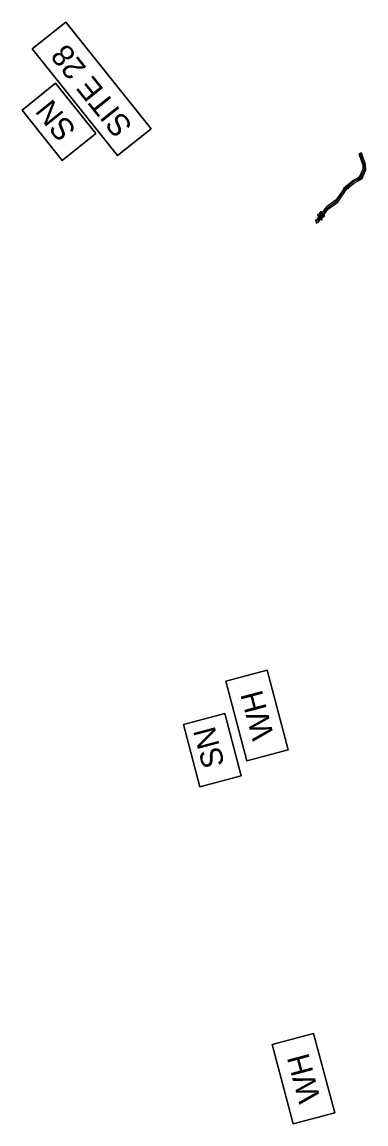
# Model space of a CAD drawing. Extents: x 474218 to 481634, y 484357 to 504997.
# Drawn here: x 474218 to 474451, y 504250 to 504997 of the extents above; entities that cross this region are included whole.
import ezdxf

# ---------------------------------------------------------------- set-up
doc = ezdxf.new("R2010")
doc.units = 0
for name, color, linetype in [('Exist Hydro Jurisdictional Stream or Body of Water', 7, 'Continuous'), ('Old_Level_29', 7, 'Continuous'), ('Old_Level_30', 7, 'Continuous'), ('Prop Earthen Structure Impacts In Surface Waters Hatching CELL', 7, 'Continuous'), ('Prop Grid Mask', 7, 'Continuous'), ('Scratch_Level_4', 7, 'Continuous'), ('Temp Earthen Structure Impacts In Surface Waters Hatching CELL', 7, 'Continuous')]:
    doc.layers.add(name, color=color, linetype=linetype)

msp = doc.modelspace()

# ---------------------------------------------------------------- linework, layer by layer
at = {"layer": 'Exist Hydro Jurisdictional Stream or Body of Water'}
for points in [[(474245.29, 504903.39), (474217.97, 504937.53), (474240.68, 504955.71), (474268, 504921.57)], [(474338.65, 504478.69), (474327.42, 504520.95), (474355.53, 504528.42), (474366.75, 504486.16)]]:
    msp.add_lwpolyline(points, close=True, dxfattribs=at)
at = {"layer": 'Old_Level_29'}
msp.add_lwpolyline([(474282.77, 504906.7), (474224.88, 504979.04), (474247.59, 504997.21), (474305.48, 504924.87)], close=True, dxfattribs=at)
at = {"layer": 'Old_Level_30'}
for points in [[(474370.47, 504496.26), (474356.14, 504550.18), (474384.25, 504557.65), (474398.57, 504503.73)], [(474402.03, 504250.05), (474387.7, 504303.96), (474415.81, 504311.43), (474430.13, 504257.51)]]:
    msp.add_lwpolyline(points, close=True, dxfattribs=at)
at = {"layer": 'Prop Earthen Structure Impacts In Surface Waters Hatching CELL'}
for p, q in [((474448.29, 504908.46), (474446.4, 504907.79)), ((474423.86, 504871.15), (474425.07, 504869.38))]:
    msp.add_line(p, q, dxfattribs=at)
for points in [[(474446.4, 504907.79), (474449.1, 504900.21), (474449.28, 504897.46), (474446.74, 504891.92), (474442.62, 504889.81), (474436.75, 504884.72), (474431, 504876.77), (474424.57, 504871.98), (474423.86, 504871.15)], [(474425.07, 504869.38), (474425.98, 504870.53), (474432.15, 504875.13), (474438.37, 504884.15), (474443.26, 504887.92), (474448.49, 504890.93), (474451.31, 504897.08), (474451.07, 504900.62), (474448.29, 504908.46)]]:
    msp.add_lwpolyline(points, dxfattribs=at)
for points in [[(474447.51, 504890.45), (474447.61, 504890.54), (474447.19, 504891.06), (474447.14, 504890.92), (474446.99, 504890.78), (474446.99, 504890.78), (474446.94, 504890.76), (474446.81, 504890.72), (474446.74, 504890.73), (474446.65, 504890.75), (474446.61, 504890.76), (474446.59, 504890.77), (474446.52, 504890.83), (474446.42, 504890.9), (474445.81, 504891.66), (474445.78, 504891.6), (474445.75, 504891.37), (474445.74, 504891.31), (474445.81, 504890.98), (474446.35, 504890.3), (474446.63, 504890.2), (474446.71, 504890.17), (474446.92, 504890.18), (474447, 504890.18), (474447.04, 504890.18), (474447.06, 504890.18), (474447.07, 504890.18), (474447.1, 504890.2), (474447.15, 504890.22), (474447.19, 504890.24), (474447.31, 504890.29), (474447.36, 504890.31), (474447.37, 504890.32)], [(474446.28, 504891.38), (474446.31, 504891.54), (474446.06, 504891.66), (474445.97, 504891.69), (474445.86, 504891.75), (474445.84, 504891.72), (474445.84, 504891.71), (474445.83, 504891.69), (474445.81, 504891.66), (474446.42, 504890.9), (474446.29, 504891.11), (474446.29, 504891.15), (474446.28, 504891.17), (474446.28, 504891.22), (474446.26, 504891.33)], [(474446.32, 504890.33), (474446.35, 504890.3), (474445.81, 504890.98), (474445.81, 504890.97), (474446.03, 504890.59), (474446.03, 504890.59)], [(474448.34, 504892.7), (474448.51, 504892.55), (474447.9, 504893.32), (474447.85, 504893.31), (474447.85, 504893.31), (474447.84, 504893.31), (474447.76, 504893.3), (474447.73, 504893.29), (474447.71, 504893.28), (474447.62, 504893.23), (474447.58, 504893.21), (474447.54, 504893.2), (474447.42, 504893.14), (474447.36, 504893.08), (474447.22, 504892.94), (474447.16, 504892.88), (474447.13, 504892.8), (474447.07, 504892.66), (474447.07, 504892.66), (474447.03, 504892.55), (474447.03, 504892.43), (474447.03, 504892.16), (474447.05, 504892.08), (474447.12, 504891.73), (474447.16, 504891.56), (474447.75, 504890.82), (474447.76, 504890.93), (474447.79, 504891.15), (474447.78, 504891.23), (474447.73, 504891.56), (474447.69, 504891.71), (474447.64, 504891.95), (474447.58, 504892.24), (474447.6, 504892.33), (474447.61, 504892.45), (474447.72, 504892.63), (474447.79, 504892.67), (474447.91, 504892.74), (474447.95, 504892.75), (474448, 504892.76), (474448.11, 504892.78), (474448.15, 504892.77), (474448.2, 504892.76), (474448.32, 504892.71), (474448.33, 504892.71)], [(474447.71, 504890.75), (474447.75, 504890.82), (474447.16, 504891.56), (474447.21, 504891.38), (474447.22, 504891.12), (474447.19, 504891.06), (474447.61, 504890.54), (474447.64, 504890.6)], [(474449.18, 504892.43), (474448.94, 504892.86), (474448.56, 504893.2), (474448.56, 504893.2), (474448.18, 504893.33), (474448.14, 504893.34), (474447.9, 504893.32), (474448.51, 504892.55), (474448.65, 504892.32), (474448.65, 504892.32), (474448.65, 504892.3), (474448.68, 504892.15), (474448.69, 504892.09), (474448.69, 504892.06), (474448.66, 504891.93), (474448.65, 504891.88), (474448.63, 504891.84), (474448.56, 504891.72), (474448.84, 504891.58), (474448.91, 504891.54), (474449.01, 504891.5), (474449.07, 504891.59), (474449.08, 504891.61), (474449.1, 504891.63), (474449.14, 504891.69), (474449.14, 504891.7), (474449.14, 504891.71), (474449.15, 504891.75), (474449.22, 504891.99), (474449.23, 504892.02), (474449.18, 504892.43)], [(474437.9, 504883.31), (474438, 504883.4), (474437.58, 504883.92), (474437.53, 504883.78), (474437.39, 504883.65), (474437.38, 504883.64), (474437.33, 504883.62), (474437.2, 504883.58), (474437.13, 504883.6), (474437.04, 504883.61), (474437, 504883.62), (474436.98, 504883.64), (474436.91, 504883.69), (474436.81, 504883.76), (474436.2, 504884.52), (474436.17, 504884.47), (474436.14, 504884.23), (474436.13, 504884.18), (474436.2, 504883.85), (474436.74, 504883.17), (474437.02, 504883.06), (474437.1, 504883.03), (474437.32, 504883.04), (474437.39, 504883.04), (474437.43, 504883.04), (474437.46, 504883.05), (474437.46, 504883.05), (474437.49, 504883.06), (474437.54, 504883.08), (474437.58, 504883.1), (474437.71, 504883.16), (474437.75, 504883.17), (474437.76, 504883.18)], [(474436.67, 504884.25), (474436.7, 504884.41), (474436.45, 504884.52), (474436.36, 504884.56), (474436.25, 504884.61), (474436.23, 504884.58), (474436.23, 504884.58), (474436.22, 504884.55), (474436.2, 504884.52), (474436.81, 504883.76), (474436.68, 504883.97), (474436.68, 504884.02), (474436.68, 504884.03), (474436.67, 504884.08), (474436.66, 504884.19)], [(474436.71, 504883.2), (474436.74, 504883.17), (474436.2, 504883.85), (474436.2, 504883.83), (474436.42, 504883.46), (474436.42, 504883.46)], [(474438.74, 504885.56), (474438.9, 504885.41), (474438.29, 504886.18), (474438.24, 504886.18), (474438.24, 504886.18), (474438.23, 504886.18), (474438.15, 504886.17), (474438.12, 504886.16), (474438.1, 504886.15), (474438.01, 504886.1), (474437.97, 504886.08), (474437.94, 504886.06), (474437.81, 504886), (474437.76, 504885.94), (474437.61, 504885.8), (474437.55, 504885.74), (474437.52, 504885.67), (474437.46, 504885.52), (474437.46, 504885.52), (474437.42, 504885.41), (474437.42, 504885.3), (474437.42, 504885.02), (474437.44, 504884.94), (474437.51, 504884.6), (474437.55, 504884.42), (474438.14, 504883.69), (474438.15, 504883.79), (474438.18, 504884.02), (474438.17, 504884.09), (474438.12, 504884.42), (474438.09, 504884.58), (474438.03, 504884.81), (474437.98, 504885.1), (474437.99, 504885.2), (474438, 504885.32), (474438.12, 504885.49), (474438.19, 504885.54), (474438.3, 504885.61), (474438.34, 504885.62), (474438.39, 504885.62), (474438.5, 504885.65), (474438.54, 504885.64), (474438.59, 504885.62), (474438.71, 504885.58), (474438.73, 504885.57)], [(474438.1, 504883.61), (474438.14, 504883.69), (474437.55, 504884.42), (474437.6, 504884.24), (474437.61, 504883.99), (474437.58, 504883.92), (474438, 504883.4), (474438.03, 504883.46)], [(474439.57, 504885.3), (474439.33, 504885.72), (474438.96, 504886.06), (474438.95, 504886.06), (474438.57, 504886.19), (474438.53, 504886.21), (474438.29, 504886.18), (474438.9, 504885.41), (474439.04, 504885.19), (474439.04, 504885.18), (474439.04, 504885.16), (474439.07, 504885.01), (474439.08, 504884.95), (474439.08, 504884.93), (474439.05, 504884.8), (474439.04, 504884.74), (474439.02, 504884.71), (474438.95, 504884.59), (474439.23, 504884.45), (474439.3, 504884.41), (474439.4, 504884.36), (474439.46, 504884.45), (474439.47, 504884.47), (474439.49, 504884.5), (474439.53, 504884.56), (474439.53, 504884.57), (474439.53, 504884.57), (474439.54, 504884.62), (474439.61, 504884.85), (474439.62, 504884.88), (474439.57, 504885.29)]]:
    msp.add_lwpolyline(points, close=True, dxfattribs=at)
at = {"layer": 'Prop Grid Mask'}
for points in [[(474305.48, 504924.87), (474247.59, 504997.21), (474224.88, 504979.04), (474282.77, 504906.7)], [(474268, 504921.57), (474240.68, 504955.71), (474217.97, 504937.53), (474245.29, 504903.39)], [(474398.57, 504503.73), (474384.25, 504557.65), (474356.14, 504550.18), (474370.47, 504496.26)], [(474366.75, 504486.16), (474355.53, 504528.42), (474327.42, 504520.95), (474338.65, 504478.69)], [(474430.13, 504257.51), (474415.81, 504311.43), (474387.7, 504303.96), (474402.03, 504250.05)]]:
    msp.add_lwpolyline(points, close=True, dxfattribs=at)
at = {"layer": 'Scratch_Level_4'}
for p, q in [((474448.29, 504908.46), (474446.4, 504907.79)), ((474423.86, 504871.15), (474425.07, 504869.38)), ((474425.07, 504869.38), (474423.88, 504871.1))]:
    msp.add_line(p, q, dxfattribs=at)
for points in [[(474446.4, 504907.79), (474449.1, 504900.21), (474449.28, 504897.46), (474446.74, 504891.92), (474442.62, 504889.81), (474436.75, 504884.72), (474431, 504876.77), (474424.57, 504871.98), (474423.86, 504871.15)], [(474424.48, 504870.24), (474425.27, 504871.26), (474431.42, 504875.84), (474437.63, 504884.85), (474442.71, 504888.76), (474447.71, 504891.64), (474450.3, 504897.27), (474450.08, 504900.41), (474447.34, 504908.12)], [(474425.07, 504869.38), (474425.98, 504870.53), (474432.15, 504875.13), (474438.37, 504884.15), (474443.26, 504887.92), (474448.49, 504890.93), (474451.31, 504897.08), (474451.07, 504900.62), (474448.29, 504908.46)], [(474424.48, 504870.3), (474418.29, 504862.42), (474417.31, 504861.85)]]:
    msp.add_lwpolyline(points, dxfattribs=at)
msp.add_lwpolyline([(474417.11, 504862.75), (474417.55, 504860.74), (474418.55, 504861.23), (474418.81, 504861.36), (474425.07, 504869.38), (474423.88, 504871.1), (474417.51, 504862.95), (474417.4, 504862.89)], close=True, dxfattribs=at)
at = {"layer": 'Temp Earthen Structure Impacts In Surface Waters Hatching CELL'}
msp.add_lwpolyline([(474417.11, 504862.75), (474417.55, 504860.74), (474418.55, 504861.23), (474418.81, 504861.36), (474425.07, 504869.38), (474423.88, 504871.1), (474417.51, 504862.95), (474417.4, 504862.89), (474417.11, 504862.75)], dxfattribs=at)
for points in [[(474421.15, 504867.88), (474421.32, 504867.73), (474420.71, 504868.49), (474420.66, 504868.49), (474420.66, 504868.49), (474420.65, 504868.49), (474420.57, 504868.48), (474420.54, 504868.47), (474420.52, 504868.46), (474420.43, 504868.41), (474420.39, 504868.39), (474420.35, 504868.37), (474420.23, 504868.31), (474420.17, 504868.25), (474420.03, 504868.11), (474419.97, 504868.05), (474419.94, 504867.98), (474419.88, 504867.84), (474419.88, 504867.83), (474419.84, 504867.72), (474419.84, 504867.61), (474419.84, 504867.33), (474419.86, 504867.25), (474419.93, 504866.91), (474419.97, 504866.73), (474420.56, 504866), (474420.57, 504866.1), (474420.6, 504866.33), (474420.59, 504866.4), (474420.54, 504866.74), (474420.5, 504866.89), (474420.45, 504867.12), (474420.39, 504867.41), (474420.41, 504867.51), (474420.42, 504867.63), (474420.53, 504867.8), (474420.6, 504867.85), (474420.72, 504867.92), (474420.76, 504867.93), (474420.81, 504867.94), (474420.92, 504867.96), (474420.96, 504867.95), (474421.01, 504867.93), (474421.13, 504867.89), (474421.14, 504867.89)], [(474421.99, 504867.61), (474421.75, 504868.03), (474421.37, 504868.38), (474421.37, 504868.38), (474420.99, 504868.5), (474420.95, 504868.52), (474420.71, 504868.49), (474421.32, 504867.73), (474421.46, 504867.5), (474421.46, 504867.49), (474421.46, 504867.47), (474421.49, 504867.32), (474421.5, 504867.27), (474421.5, 504867.24), (474421.47, 504867.11), (474421.46, 504867.05), (474421.44, 504867.02), (474421.37, 504866.9), (474421.65, 504866.76), (474421.72, 504866.72), (474421.82, 504866.67), (474421.88, 504866.76), (474421.89, 504866.78), (474421.91, 504866.81), (474421.95, 504866.87), (474421.95, 504866.88), (474421.95, 504866.88), (474421.96, 504866.93), (474422.03, 504867.16), (474422.04, 504867.2), (474421.99, 504867.6)], [(474420.32, 504865.63), (474420.42, 504865.71), (474420, 504866.23), (474419.95, 504866.09), (474419.8, 504865.96), (474419.8, 504865.95), (474419.75, 504865.94), (474419.62, 504865.9), (474419.55, 504865.91), (474419.46, 504865.93), (474419.42, 504865.93), (474419.4, 504865.95), (474419.33, 504866), (474419.23, 504866.08), (474418.62, 504866.84), (474418.59, 504866.78), (474418.56, 504866.54), (474418.55, 504866.49), (474418.62, 504866.16), (474419.16, 504865.48), (474419.44, 504865.37), (474419.52, 504865.34), (474419.73, 504865.35), (474419.81, 504865.35), (474419.85, 504865.36), (474419.87, 504865.36), (474419.88, 504865.36), (474419.91, 504865.37), (474419.96, 504865.4), (474420, 504865.41), (474420.12, 504865.47), (474420.17, 504865.49), (474420.18, 504865.49)], [(474419.09, 504866.56), (474419.12, 504866.72), (474418.87, 504866.83), (474418.78, 504866.87), (474418.67, 504866.92), (474418.65, 504866.89), (474418.65, 504866.89), (474418.64, 504866.87), (474418.62, 504866.84), (474419.23, 504866.08), (474419.1, 504866.29), (474419.1, 504866.33), (474419.09, 504866.34), (474419.09, 504866.39), (474419.07, 504866.51)], [(474419.13, 504865.51), (474419.16, 504865.48), (474418.62, 504866.16), (474418.62, 504866.15), (474418.84, 504865.77), (474418.84, 504865.77)], [(474421.29, 504862.84), (474421.67, 504863.14), (474420.16, 504865.04), (474419.77, 504864.73)], [(474420.52, 504865.92), (474420.56, 504866), (474419.97, 504866.73), (474420.02, 504866.55), (474420.03, 504866.3), (474420, 504866.23), (474420.42, 504865.71), (474420.45, 504865.77)], [(474421.09, 504863.87), (474423.45, 504865.76), (474423.1, 504866.2), (474420.74, 504864.31)]]:
    msp.add_lwpolyline(points, close=True, dxfattribs=at)

# ---------------------------------------------------------------- texts
at = {"layer": 'Exist Hydro Jurisdictional Stream or Body of Water'}
for rotation, p in [(128.67157, (474255.35, 504924.16)), (104.8782, (474355.59, 504493.68))]:
    msp.add_text('SN', height=15, rotation=rotation, dxfattribs=at).set_placement(p)
at = {"layer": 'Old_Level_29'}
msp.add_text('SITE 28', height=15, rotation=128.67157, dxfattribs=at).set_placement((474293.52, 504926.87))
at = {"layer": 'Old_Level_30'}
for p in [(474389.06, 504512.95), (474420.62, 504266.73)]:
    msp.add_text('WH', height=15, rotation=104.8782, dxfattribs=at).set_placement(p)

doc.saveas('drawing.dxf')
